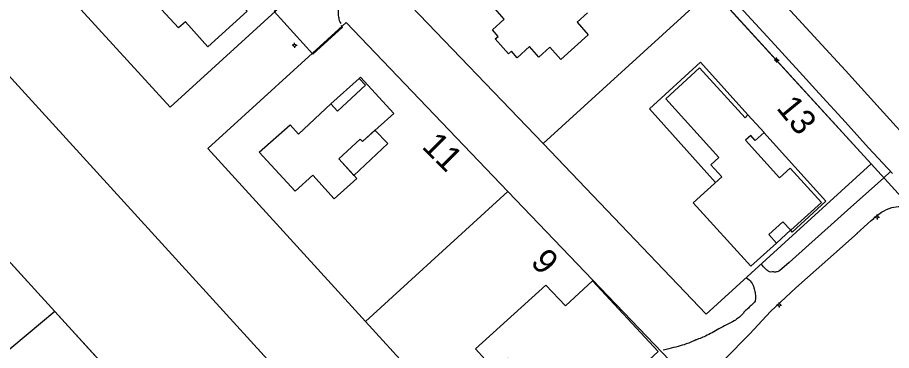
# Model space of a CAD drawing. Extents: x 1517229 to 1518128, y 6494851 to 6495271.
# Drawn here: x 1517875.8 to 1518015.9, y 6495126.7 to 6495180.1 of the extents above; entities that cross this region are included whole.
import ezdxf

# ---------------------------------------------------------------- set-up
doc = ezdxf.new("R2010")
doc.units = 0
doc.layers.add('Karta', color=7, linetype='Continuous')

msp = doc.modelspace()

# ---------------------------------------------------------------- linework, layer by layer
at = {"layer": 'Karta'}
for p, q in [((1517900.25, 6495165.74), (1517877.68, 6495190.48)), ((1517860.04, 6495186.49), (1518013.12, 6495018.67)), ((1517922.42, 6495185.95), (1517900.25, 6495165.74)), ((1517960.06, 6495159.9), (1517935.42, 6495185.63)), ((1517987.15, 6495184.61), (1517960.06, 6495159.9)), ((1518012.65, 6495156.65), (1517987.15, 6495184.61)), ((1517906.32, 6495159.09), (1517928.49, 6495179.31)), ((1517928.49, 6495179.31), (1517954.43, 6495152.21)), ((1517920.02, 6495175.67), (1517919.82, 6495175.67)), ((1517920.22, 6495175.87), (1517920.22, 6495176.07)), ((1517920.42, 6495175.67), (1517920.62, 6495175.67)), ((1517920.22, 6495175.47), (1517920.22, 6495175.27)), ((1517844.68, 6495173.66), (1517881.78, 6495132.98)), ((1517985.3, 6495172.94), (1517992.9, 6495164.5)), ((1517997.31, 6495173.28), (1517997.11, 6495173.28)), ((1517997.51, 6495173.48), (1517997.51, 6495173.68)), ((1517997.51, 6495173.08), (1517997.51, 6495172.88)), ((1517997.71, 6495173.28), (1517997.91, 6495173.28)), ((1517926.06, 6495166.25), (1517930.6, 6495170.36)), ((1517931.59, 6495131.38), (1517906.32, 6495159.09)), ((1517960.06, 6495159.9), (1517986.23, 6495132.56)), ((1517986.23, 6495132.56), (1518012.65, 6495156.65)), ((1518012.65, 6495156.65), (1518038.97, 6495127.79)), ((1517954.43, 6495152.21), (1517931.59, 6495131.38)), ((1517980.37, 6495125.12), (1517954.43, 6495152.21)), ((1518013.41, 6495148.11), (1518013.21, 6495148.11)), ((1518013.61, 6495148.31), (1518013.61, 6495148.51)), ((1518013.61, 6495147.91), (1518013.61, 6495147.71)), ((1518013.81, 6495148.11), (1518014.01, 6495148.11)), ((1518010.39, 6495145.49), (1518012.69, 6495147.54)), ((1517999.76, 6495146.01), (1517997.51, 6495143.95)), ((1517997.71, 6495133.99), (1517997.51, 6495133.99)), ((1517997.91, 6495134.19), (1517997.91, 6495134.39)), ((1517997.91, 6495133.79), (1517997.91, 6495133.59)), ((1517998.11, 6495133.99), (1517998.31, 6495133.99)), ((1517881.78, 6495132.98), (1517826.66, 6495086.92)), ((1517881.78, 6495132.98), (1517993.7, 6495010.28)), ((1517931.59, 6495131.38), (1517956.86, 6495103.68))]:
    msp.add_line(p, q, dxfattribs=at)
for points in [[(1517963.15, 6495210.92), (1517987.15, 6495184.61), (1518012.65, 6495156.65)], [(1517892.51, 6495191.99), (1517898.1, 6495197.09), (1517905.02, 6495189.5), (1517905.77, 6495190.12), (1517908.77, 6495186.9), (1517908, 6495186.22), (1517912.61, 6495181.16), (1517906.31, 6495175.43), (1517902.71, 6495179.4), (1517901.62, 6495178.44), (1517897.5, 6495182.9), (1517899.28, 6495184.6), (1517892.51, 6495191.99)], [(1517987.66, 6495186.25), (1517992.87, 6495180.52), (1517996.66, 6495176.39), (1518001.2, 6495171.42)], [(1517994.66, 6495186.79), (1517999.17, 6495181.82), (1518004.14, 6495176.43), (1518008.54, 6495171.61)], [(1517927.68, 6495178.87), (1517927.87, 6495178.53), (1517923.16, 6495174.23), (1517916.97, 6495181.1), (1517921.05, 6495184.84)], [(1517967.2, 6495180.87), (1517965.54, 6495179.37), (1517967.31, 6495177.32), (1517962.93, 6495173.39), (1517961.16, 6495175.34), (1517959.41, 6495173.76), (1517957.91, 6495175.45), (1517955.93, 6495173.65), (1517954.98, 6495174.73), (1517954.54, 6495174.29), (1517952.4, 6495176.69), (1517952.86, 6495177.09), (1517951.95, 6495178.12), (1517953.83, 6495179.86), (1517952.31, 6495181.55)], [(1517844.68, 6495173.66), (1517881.78, 6495132.98), (1517993.7, 6495010.28)], [(1517987.74, 6495153.68), (1517977.11, 6495165.49), (1517985.3, 6495172.95)], [(1517979.74, 6495167.07), (1517985.16, 6495172.05), (1517992.45, 6495164.05), (1517992.9, 6495164.51), (1517995.5, 6495161.65), (1517994.06, 6495160.37), (1517993.36, 6495161.2), (1517992.5, 6495160.45), (1517997.97, 6495154.38), (1517999.7, 6495155.94), (1518004.69, 6495150.46), (1517999.77, 6495146.01), (1517998.49, 6495147.37), (1517996.24, 6495145.33), (1517997.51, 6495143.95), (1517993.39, 6495140.21), (1517984.12, 6495150.38), (1517988.71, 6495154.55), (1517986.96, 6495156.5), (1517988.24, 6495157.69), (1517979.74, 6495167.07)], [(1518008.54, 6495171.61), (1518012.11, 6495167.69), (1518016.69, 6495162.63), (1518020.21, 6495158.78), (1518023.27, 6495155.38)], [(1517914.57, 6495158.53), (1517919.49, 6495162.9), (1517920.83, 6495161.43), (1517926.06, 6495166.25), (1517927.11, 6495165.11), (1517931.61, 6495169.27), (1517930.6, 6495170.36), (1517930.82, 6495170.56), (1517936.12, 6495164.72), (1517931.1, 6495160.24), (1517930.75, 6495160.6), (1517927.33, 6495157.45), (1517930.2, 6495154.27), (1517926.55, 6495151.04), (1517923.14, 6495154.82), (1517920.31, 6495152.25), (1517914.57, 6495158.53)], [(1518001.2, 6495171.42), (1518004.36, 6495167.91), (1518008.54, 6495163.33), (1518012.27, 6495159.23), (1518016.09, 6495155.08)], [(1517927.33, 6495157.45), (1517930.75, 6495160.6), (1517931.1, 6495160.24), (1517933.11, 6495162.03), (1517935.2, 6495159.89), (1517929.75, 6495154.77), (1517927.79, 6495156.94)], [(1517995.49, 6495161.65), (1518005.41, 6495150.64), (1518000.03, 6495145.71), (1517999.77, 6495146.01)], [(1518015.79, 6495155.4), (1518014.64, 6495154.36), (1518009.4, 6495149.68), (1518004.73, 6495145.46), (1518002.7, 6495143.65)], [(1517993.24, 6495129.4), (1517996.55, 6495132.94), (1518000.62, 6495136.74), (1518005.75, 6495141.33), (1518010.46, 6495145.55)], [(1518002.7, 6495143.65), (1517999.52, 6495140.84), (1517997.98, 6495139.49)], [(1517949.24, 6495126.98), (1517960.49, 6495137.19), (1517963.66, 6495133.86), (1517967.99, 6495137.88), (1517978.54, 6495126.55), (1517967.29, 6495116.15), (1517968.76, 6495114.56), (1517961.02, 6495107.55), (1517961.18, 6495107.37), (1517957.48, 6495104.06), (1517952.53, 6495109.56), (1517961.53, 6495117.85), (1517954.49, 6495125.49), (1517952.35, 6495123.56), (1517949.24, 6495126.99)], [(1517980.9, 6495116.52), (1517980.87, 6495116.58), (1517985.09, 6495121.02), (1517989.01, 6495125.09), (1517993.39, 6495129.56)]]:
    msp.add_lwpolyline(points, dxfattribs=at)
for centre in [(1517920.22, 6495175.67), (1517997.51, 6495173.28), (1518013.61, 6495148.11), (1517997.91, 6495133.99)]:
    msp.add_circle(centre, 0.2, dxfattribs=at)
for points in [[(1517928.63, 6495183.37), (1517927.6, 6495182.34), (1517927.23, 6495181.53), (1517927.21, 6495180.66), (1517927.34, 6495179.84), (1517927.47, 6495179.45), (1517927.63, 6495179.16)], [(1518012.69, 6495147.54), (1518014.35, 6495148.9), (1518015.98, 6495149.62), (1518017.39, 6495149.81), (1518018.33, 6495149.68), (1518019.08, 6495149.47), (1518019.56, 6495149.05)], [(1517997.98, 6495139.49), (1517997.5, 6495139.3), (1517996.84, 6495139.3), (1517996.39, 6495139.3), (1517996.2, 6495139.42), (1517995.81, 6495139.73), (1517995.09, 6495140.54)], [(1517992.66, 6495138.37), (1517993.45, 6495137.68), (1517993.87, 6495136.77), (1517994.08, 6495135.99), (1517994.11, 6495135.17), (1517994.05, 6495134.63), (1517993.57, 6495134.08), (1517992.99, 6495133.51), (1517992.39, 6495132.97), (1517991.97, 6495132.46), (1517991.39, 6495131.94), (1517990.73, 6495131.49), (1517989.49, 6495130.83), (1517988.26, 6495130.16), (1517986.12, 6495129.02), (1517984.34, 6495128.32)], [(1517984.65, 6495128.44), (1517983.02, 6495127.75), (1517981.73, 6495127.36), (1517980.25, 6495126.99), (1517979.35, 6495126.78)]]:
    msp.add_spline(points, degree=3, dxfattribs=at)

# ---------------------------------------------------------------- texts
for s, rotation, p in [('13', 309.455, (1517997.35, 6495165.56)), ('11', 314.9833, (1517940.46, 6495159.3)), ('9', 311.9627, (1517957.91, 6495140.78))]:
    msp.add_text(s, height=4, rotation=rotation, dxfattribs=at).set_placement(p)

doc.saveas('drawing.dxf')
